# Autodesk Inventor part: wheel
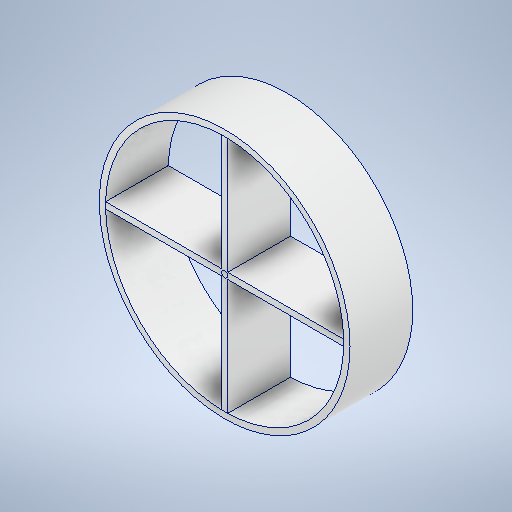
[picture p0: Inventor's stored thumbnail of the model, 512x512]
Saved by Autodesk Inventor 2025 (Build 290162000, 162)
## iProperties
Created: 2024-09
Part Number: wheel
Material: Aluminum 6061
Document SubType Name: Modeling
Designer: aryas
Density: 2.7 g/cm^3
Appearance: Aluminum - Flat
Author: aryas
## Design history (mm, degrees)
sketch "Sketch1"
  geometry: L1 (-2.5, 0)-(-2.5, 94.967); L2 (2.5, 0)-(2.5, 94.967); L3 (-2.5, 94.967)-(2.5, 94.967); L4 (-2.5, -94.967)-(2.5, -94.967); L5 (2.5, -94.967)-(2.5, 0); L6 (2.5, 0)-(-2.5, 0); L7 (-2.5, 0)-(-2.5, -94.967); L8 (0, 2.5)-(0, -2.5); L9 (0, -2.5)-(95, -2.5); L10 (95, -2.5)-(95, 2.5); L11 (95, 2.5)-(0, 2.5); L12 (0, 2.5)-(0, -2.5); L13 (0, -2.5)-(-95, -2.5); L14 (-95, -2.5)-(-95, 2.5); L15 (-95, 2.5)-(0, 2.5); C1 r 100 at (0, 0); A1 r 95 centre (0, 0) between (-2.5, 94.967) and (2.5, 94.967); A2 r 2.5 centre (0, 0) between (-2.5, 0) and (2.5, 0); 12 further points
  constraints: 30 end point, 8 point on circle, 7 equal length, 4 perpendicular, 3 centre point, 3 coincident, 3 vertical, 1 midpoint, 1 tangent
  dimensions: "d0" = 200 diameter of C1; "d1" = 190 diameter of A1; "d2" = 5 diameter of A2; "d3" = 5 distance between parallel lines of L5 L7; "d4" = 0 distance of point (0, 0) point (0, 0); "d5" = 0 distance of point (0, 0) point (0, 0); "d6" = 5 distance between parallel lines of L9 L11
extrude "Extrusion1" new body sketch "Sketch1" distance "d7" = 50; taper "d8" = 0 deg
body "Solid1"
